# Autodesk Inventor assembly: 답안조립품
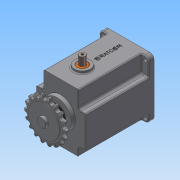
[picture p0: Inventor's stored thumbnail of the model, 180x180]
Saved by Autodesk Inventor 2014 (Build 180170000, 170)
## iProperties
Created: 2016-05
Part Number: 답안조립품
Document SubType Name: Assembly
Designer: 703-04
Author: 703-04
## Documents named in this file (16)
- C:\Users\703-04\Desktop\360508V1007\답안조립품.iam
- C:\Users\703-04\Desktop\360508V1007\본체.ipt
- C:\Users\703-04\Desktop\360508V1007\커버.ipt
- C:\Users\703-04\Desktop\360508V1007\서브축.ipt
- C:\Users\703-04\Desktop\360508V1007\오일실 8 22 7.ipt
- C:\Users\703-04\Desktop\360508V1007\오일실 17 32 8.ipt
- C:\Users\703-04\Desktop\360508V1007\베어링 608.ipt
- C:\Users\703-04\Desktop\360508V1007\베어링 6003.ipt
- C:\Users\703-04\Desktop\360508V1007\메인축.ipt
- C:\Users\703-04\Desktop\360508V1007\키 5 x 5 x 18.ipt
- C:\Users\703-04\Desktop\360508V1007\가변 스프링.ipt
- C:\Users\703-04\Desktop\360508V1007\볼트 M4 x 10.ipt
- C:\Users\703-04\Desktop\360508V1007\부시.ipt
- C:\Users\703-04\Desktop\360508V1007\스프로킷.ipt
- C:\Users\703-04\Desktop\360508V1007\슬라이더.ipt
- C:\Users\703-04\Desktop\360508V1007\멈춤나사 M3x8.ipt
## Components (3 placed, 2 different names)
1. 가변 스프링:1
2. ISO 4762 M4 x 10:1
3. ISO 4762 M4 x 10:2
